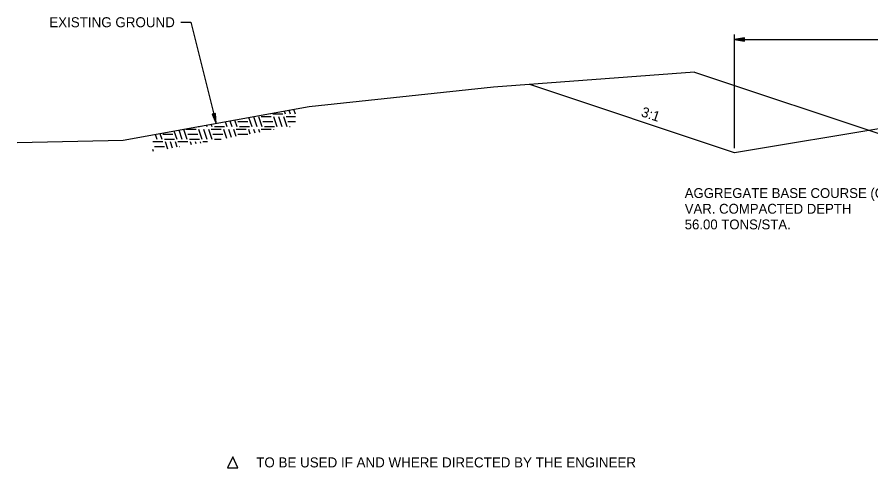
# Model space of a CAD drawing. Extents: x 1824008 to 1828864, y 689441 to 689870.
# Drawn here: x 1828711.2 to 1828762.4, y 689824.6 to 689851.6 of the extents above; entities that cross this region are included whole.
import ezdxf

# ---------------------------------------------------------------- set-up
doc = ezdxf.new("R2010")
doc.units = 0
for name, color, linetype in [('1', 7, 'Continuous'), ('19', 7, 'Continuous'), ('R_Draft', 7, 'Continuous')]:
    doc.layers.add(name, color=color, linetype=linetype)

msp = doc.modelspace()

# ---------------------------------------------------------------- linework, layer by layer
at = {"layer": '1'}
for p, q in [((1828754.22, 689843.791), (1828754.22, 689850.607)), ((1828754.82, 689850.412), (1828754.22, 689850.307)), ((1828754.22, 689850.307), (1828774.22, 689850.307)), ((1828754.22, 689850.307), (1828754.82, 689850.202)), ((1828754.82, 689850.357), (1828754.38, 689850.322)), ((1828754.38, 689850.292), (1828754.82, 689850.252)), ((1828754.82, 689850.202), (1828754.82, 689850.412)), ((1828751.824, 689848.348), (1828765.008, 689843.953)), ((1828754.22, 689843.509), (1828741.942, 689847.602)), ((1828727.883, 689845.828), (1828727.789, 689846.109)), ((1828727.883, 689845.828), (1828727.789, 689846.109)), ((1828727.883, 689845.828), (1828727.789, 689846.109)), ((1828723.09, 689845.872), (1828722.888, 689845.821)), ((1828722.888, 689845.821), (1828723.134, 689845.265)), ((1828722.933, 689845.829), (1828723.08, 689845.417)), ((1828723.105, 689845.421), (1828723.039, 689845.854)), ((1828723.134, 689845.265), (1828723.09, 689845.872)), ((1828725.286, 689845.069), (1828725.101, 689845.622)), ((1828725.286, 689845.069), (1828725.101, 689845.622)), ((1828725.286, 689845.069), (1828725.101, 689845.622)), ((1828725.586, 689845.069), (1828725.386, 689845.669)), ((1828725.586, 689845.069), (1828725.386, 689845.669)), ((1828725.586, 689845.069), (1828725.386, 689845.669)), ((1828725.886, 689845.069), (1828725.686, 689845.669)), ((1828725.886, 689845.069), (1828725.686, 689845.669)), ((1828725.886, 689845.069), (1828725.686, 689845.669)), ((1828726.436, 689845.669), (1828725.836, 689845.669)), ((1828726.436, 689845.669), (1828725.836, 689845.669)), ((1828726.436, 689845.669), (1828725.836, 689845.669)), ((1828726.386, 689845.819), (1828726.374, 689845.852)), ((1828726.386, 689845.819), (1828726.374, 689845.852)), ((1828726.386, 689845.819), (1828726.374, 689845.852)), ((1828727.136, 689845.819), (1828726.536, 689845.819)), ((1828727.136, 689845.819), (1828726.536, 689845.819)), ((1828727.136, 689845.819), (1828726.536, 689845.819)), ((1828726.786, 689845.069), (1828726.586, 689845.669)), ((1828726.786, 689845.069), (1828726.586, 689845.669)), ((1828726.786, 689845.069), (1828726.586, 689845.669)), ((1828727.086, 689845.069), (1828726.886, 689845.669)), ((1828727.086, 689845.069), (1828726.886, 689845.669)), ((1828727.086, 689845.069), (1828726.886, 689845.669)), ((1828727.386, 689845.069), (1828727.186, 689845.669)), ((1828727.386, 689845.069), (1828727.186, 689845.669)), ((1828727.386, 689845.069), (1828727.186, 689845.669)), ((1828727.286, 689845.819), (1828727.223, 689846.006)), ((1828727.286, 689845.819), (1828727.223, 689846.006)), ((1828727.286, 689845.819), (1828727.223, 689846.006)), ((1828727.386, 689845.669), (1828727.336, 689845.669)), ((1828727.386, 689845.669), (1828727.336, 689845.669)), ((1828727.386, 689845.669), (1828727.336, 689845.669)), ((1828727.883, 689845.669), (1828727.386, 689845.669)), ((1828727.883, 689845.669), (1828727.386, 689845.669)), ((1828727.883, 689845.669), (1828727.386, 689845.669)), ((1828727.586, 689845.819), (1828727.506, 689846.058)), ((1828727.586, 689845.819), (1828727.506, 689846.058)), ((1828727.586, 689845.819), (1828727.506, 689846.058)), ((1828722.286, 689845.069), (1828722.272, 689845.109)), ((1828722.286, 689845.069), (1828722.272, 689845.109)), ((1828722.286, 689845.069), (1828722.272, 689845.109)), ((1828722.586, 689845.069), (1828722.555, 689845.16)), ((1828722.586, 689845.069), (1828722.555, 689845.16)), ((1828722.586, 689845.069), (1828722.555, 689845.16)), ((1828722.886, 689845.069), (1828722.838, 689845.211)), ((1828722.886, 689845.069), (1828722.838, 689845.211)), ((1828722.886, 689845.069), (1828722.838, 689845.211)), ((1828723.786, 689845.069), (1828723.687, 689845.365)), ((1828723.786, 689845.069), (1828723.687, 689845.365)), ((1828723.786, 689845.069), (1828723.687, 689845.365)), ((1828724.086, 689845.069), (1828723.97, 689845.416)), ((1828724.086, 689845.069), (1828723.97, 689845.416)), ((1828724.086, 689845.069), (1828723.97, 689845.416)), ((1828724.386, 689845.069), (1828724.253, 689845.468)), ((1828724.386, 689845.069), (1828724.253, 689845.468)), ((1828724.386, 689845.069), (1828724.253, 689845.468)), ((1828725.036, 689845.369), (1828724.436, 689845.369)), ((1828725.036, 689845.369), (1828724.436, 689845.369)), ((1828725.036, 689845.369), (1828724.436, 689845.369)), ((1828726.536, 689845.369), (1828725.936, 689845.369)), ((1828726.536, 689845.369), (1828725.936, 689845.369)), ((1828726.536, 689845.369), (1828725.936, 689845.369)), ((1828727.883, 689845.369), (1828727.436, 689845.369)), ((1828727.883, 689845.369), (1828727.436, 689845.369)), ((1828727.883, 689845.369), (1828727.436, 689845.369)), ((1828719.586, 689844.319), (1828719.49, 689844.604)), ((1828719.586, 689844.319), (1828719.49, 689844.604)), ((1828719.586, 689844.319), (1828719.49, 689844.604)), ((1828719.886, 689844.319), (1828719.773, 689844.655)), ((1828719.886, 689844.319), (1828719.773, 689844.655)), ((1828719.886, 689844.319), (1828719.773, 689844.655)), ((1828720.536, 689844.619), (1828719.936, 689844.619)), ((1828720.536, 689844.619), (1828719.936, 689844.619)), ((1828720.536, 689844.619), (1828719.936, 689844.619)), ((1828720.786, 689844.319), (1828720.622, 689844.809)), ((1828720.786, 689844.319), (1828720.622, 689844.809)), ((1828720.786, 689844.319), (1828720.622, 689844.809)), ((1828721.086, 689844.319), (1828720.905, 689844.861)), ((1828721.086, 689844.319), (1828720.905, 689844.861)), ((1828721.086, 689844.319), (1828720.905, 689844.861)), ((1828721.386, 689844.319), (1828721.188, 689844.912)), ((1828721.386, 689844.319), (1828721.188, 689844.912)), ((1828721.386, 689844.319), (1828721.188, 689844.912)), ((1828721.386, 689844.919), (1828721.336, 689844.919)), ((1828721.386, 689844.919), (1828721.336, 689844.919)), ((1828721.386, 689844.919), (1828721.336, 689844.919)), ((1828721.936, 689844.919), (1828721.386, 689844.919)), ((1828721.936, 689844.919), (1828721.386, 689844.919)), ((1828721.936, 689844.919), (1828721.386, 689844.919)), ((1828722.036, 689844.619), (1828721.436, 689844.619)), ((1828722.036, 689844.619), (1828721.436, 689844.619)), ((1828722.036, 689844.619), (1828721.436, 689844.619)), ((1828722.136, 689845.069), (1828722.053, 689845.069)), ((1828722.136, 689845.069), (1828722.053, 689845.069)), ((1828722.136, 689845.069), (1828722.053, 689845.069)), ((1828722.286, 689844.319), (1828722.086, 689844.919)), ((1828722.286, 689844.319), (1828722.086, 689844.919)), ((1828722.286, 689844.319), (1828722.086, 689844.919)), ((1828722.586, 689844.319), (1828722.386, 689844.919)), ((1828722.586, 689844.319), (1828722.386, 689844.919)), ((1828722.586, 689844.319), (1828722.386, 689844.919)), ((1828722.886, 689844.319), (1828722.686, 689844.919)), ((1828722.886, 689844.319), (1828722.686, 689844.919)), ((1828722.886, 689844.319), (1828722.686, 689844.919)), ((1828723.436, 689844.919), (1828722.836, 689844.919)), ((1828723.436, 689844.919), (1828722.836, 689844.919)), ((1828723.436, 689844.919), (1828722.836, 689844.919)), ((1828723.536, 689844.619), (1828722.936, 689844.619)), ((1828723.536, 689844.619), (1828722.936, 689844.619)), ((1828723.536, 689844.619), (1828722.936, 689844.619)), ((1828723.636, 689845.069), (1828723.036, 689845.069)), ((1828723.636, 689845.069), (1828723.036, 689845.069)), ((1828723.636, 689845.069), (1828723.036, 689845.069)), ((1828723.765, 689844.379), (1828723.586, 689844.919)), ((1828723.765, 689844.379), (1828723.586, 689844.919)), ((1828723.765, 689844.379), (1828723.586, 689844.919)), ((1828724.048, 689844.431), (1828723.886, 689844.919)), ((1828724.048, 689844.431), (1828723.886, 689844.919)), ((1828724.048, 689844.431), (1828723.886, 689844.919)), ((1828724.331, 689844.482), (1828724.186, 689844.919)), ((1828724.331, 689844.482), (1828724.186, 689844.919)), ((1828724.331, 689844.482), (1828724.186, 689844.919)), ((1828724.386, 689844.919), (1828724.336, 689844.919)), ((1828724.386, 689844.919), (1828724.336, 689844.919)), ((1828724.386, 689844.919), (1828724.336, 689844.919)), ((1828724.936, 689844.919), (1828724.386, 689844.919)), ((1828724.936, 689844.919), (1828724.386, 689844.919)), ((1828724.936, 689844.919), (1828724.386, 689844.919)), ((1828725.036, 689844.619), (1828724.436, 689844.619)), ((1828725.036, 689844.619), (1828724.436, 689844.619)), ((1828725.036, 689844.619), (1828724.436, 689844.619)), ((1828725.136, 689845.069), (1828724.536, 689845.069)), ((1828725.136, 689845.069), (1828724.536, 689845.069)), ((1828725.136, 689845.069), (1828724.536, 689845.069)), ((1828725.18, 689844.636), (1828725.086, 689844.919)), ((1828725.18, 689844.636), (1828725.086, 689844.919)), ((1828725.18, 689844.636), (1828725.086, 689844.919)), ((1828725.463, 689844.687), (1828725.386, 689844.919)), ((1828725.463, 689844.687), (1828725.386, 689844.919)), ((1828725.463, 689844.687), (1828725.386, 689844.919)), ((1828725.746, 689844.738), (1828725.686, 689844.919)), ((1828725.746, 689844.738), (1828725.686, 689844.919)), ((1828725.746, 689844.738), (1828725.686, 689844.919)), ((1828726.436, 689844.919), (1828725.836, 689844.919)), ((1828726.436, 689844.919), (1828725.836, 689844.919)), ((1828726.436, 689844.919), (1828725.836, 689844.919)), ((1828726.636, 689845.069), (1828726.036, 689845.069)), ((1828726.636, 689845.069), (1828726.036, 689845.069)), ((1828726.636, 689845.069), (1828726.036, 689845.069)), ((1828726.594, 689844.892), (1828726.586, 689844.919)), ((1828726.594, 689844.892), (1828726.586, 689844.919)), ((1828726.594, 689844.892), (1828726.586, 689844.919)), ((1828727.568, 689845.069), (1828727.536, 689845.069)), ((1828727.568, 689845.069), (1828727.536, 689845.069)), ((1828727.568, 689845.069), (1828727.536, 689845.069)), ((1828719.936, 689844.169), (1828719.336, 689844.169)), ((1828719.936, 689844.169), (1828719.336, 689844.169)), ((1828719.936, 689844.169), (1828719.336, 689844.169)), ((1828720.636, 689844.319), (1828720.036, 689844.319)), ((1828720.636, 689844.319), (1828720.036, 689844.319)), ((1828720.636, 689844.319), (1828720.036, 689844.319)), ((1828720.229, 689843.738), (1828720.086, 689844.169)), ((1828720.229, 689843.738), (1828720.086, 689844.169)), ((1828720.229, 689843.738), (1828720.086, 689844.169)), ((1828720.512, 689843.789), (1828720.386, 689844.169)), ((1828720.512, 689843.789), (1828720.386, 689844.169)), ((1828720.512, 689843.789), (1828720.386, 689844.169)), ((1828720.795, 689843.841), (1828720.686, 689844.169)), ((1828720.795, 689843.841), (1828720.686, 689844.169)), ((1828720.795, 689843.841), (1828720.686, 689844.169)), ((1828721.386, 689844.169), (1828720.836, 689844.169)), ((1828721.386, 689844.169), (1828720.836, 689844.169)), ((1828721.386, 689844.169), (1828720.836, 689844.169)), ((1828721.436, 689844.169), (1828721.386, 689844.169)), ((1828721.436, 689844.169), (1828721.386, 689844.169)), ((1828721.436, 689844.169), (1828721.386, 689844.169)), ((1828722.136, 689844.319), (1828721.536, 689844.319)), ((1828722.136, 689844.319), (1828721.536, 689844.319)), ((1828722.136, 689844.319), (1828721.536, 689844.319)), ((1828721.644, 689843.995), (1828721.586, 689844.169)), ((1828721.644, 689843.995), (1828721.586, 689844.169)), ((1828721.644, 689843.995), (1828721.586, 689844.169)), ((1828721.927, 689844.046), (1828721.886, 689844.169)), ((1828721.927, 689844.046), (1828721.886, 689844.169)), ((1828721.927, 689844.046), (1828721.886, 689844.169)), ((1828722.209, 689844.097), (1828722.186, 689844.169)), ((1828722.209, 689844.097), (1828722.186, 689844.169)), ((1828722.209, 689844.097), (1828722.186, 689844.169)), ((1828722.604, 689844.169), (1828722.336, 689844.169)), ((1828722.604, 689844.169), (1828722.336, 689844.169)), ((1828722.604, 689844.169), (1828722.336, 689844.169)), ((1828723.431, 689844.319), (1828723.036, 689844.319)), ((1828723.431, 689844.319), (1828723.036, 689844.319)), ((1828723.431, 689844.319), (1828723.036, 689844.319)), ((1828719.38, 689843.584), (1828719.336, 689843.717)), ((1828719.38, 689843.584), (1828719.336, 689843.717)), ((1828719.38, 689843.584), (1828719.336, 689843.717)), ((1828720.036, 689843.869), (1828719.436, 689843.869)), ((1828720.036, 689843.869), (1828719.436, 689843.869)), ((1828720.036, 689843.869), (1828719.436, 689843.869)), ((1828720.95, 689843.869), (1828720.936, 689843.869)), ((1828720.95, 689843.869), (1828720.936, 689843.869)), ((1828720.95, 689843.869), (1828720.936, 689843.869))]:
    msp.add_line(p, q, dxfattribs=at)
for points in [[(1828721.022, 689851.338), (1828721.622, 689851.338), (1828723.134, 689845.265)], [(1828751.824, 689848.348), (1828739.772, 689847.438), (1828728.716, 689846.277), (1828717.551, 689844.253), (1828711.19, 689844.117)]]:
    msp.add_lwpolyline(points, dxfattribs=at)
at = {"layer": '19'}
for p, q in [((1828770.22, 689846.176), (1828754.22, 689843.509)), ((1828724.134, 689825.297), (1828723.816, 689824.626)), ((1828724.427, 689824.626), (1828724.134, 689825.297)), ((1828723.816, 689824.626), (1828724.427, 689824.626))]:
    msp.add_line(p, q, dxfattribs=at)
at = {"layer": 'R_Draft'}
for p, q in [((1828727.883, 689845.828), (1828727.789, 689846.109)), ((1828725.286, 689845.069), (1828725.101, 689845.622)), ((1828725.586, 689845.069), (1828725.386, 689845.669)), ((1828725.886, 689845.069), (1828725.686, 689845.669)), ((1828726.436, 689845.669), (1828725.836, 689845.669)), ((1828726.386, 689845.819), (1828726.374, 689845.852)), ((1828727.136, 689845.819), (1828726.536, 689845.819)), ((1828726.786, 689845.069), (1828726.586, 689845.669)), ((1828727.086, 689845.069), (1828726.886, 689845.669)), ((1828727.386, 689845.069), (1828727.186, 689845.669)), ((1828727.286, 689845.819), (1828727.223, 689846.006)), ((1828727.386, 689845.669), (1828727.336, 689845.669)), ((1828727.883, 689845.669), (1828727.386, 689845.669)), ((1828727.586, 689845.819), (1828727.506, 689846.058)), ((1828722.286, 689845.069), (1828722.272, 689845.109)), ((1828722.586, 689845.069), (1828722.555, 689845.16)), ((1828722.886, 689845.069), (1828722.838, 689845.211)), ((1828723.786, 689845.069), (1828723.687, 689845.365)), ((1828724.086, 689845.069), (1828723.97, 689845.416)), ((1828724.386, 689845.069), (1828724.253, 689845.468)), ((1828725.036, 689845.369), (1828724.436, 689845.369)), ((1828726.536, 689845.369), (1828725.936, 689845.369)), ((1828727.883, 689845.369), (1828727.436, 689845.369)), ((1828719.586, 689844.319), (1828719.49, 689844.604)), ((1828719.886, 689844.319), (1828719.773, 689844.655)), ((1828720.536, 689844.619), (1828719.936, 689844.619)), ((1828720.786, 689844.319), (1828720.622, 689844.809)), ((1828721.086, 689844.319), (1828720.905, 689844.861)), ((1828721.386, 689844.319), (1828721.188, 689844.912)), ((1828721.386, 689844.919), (1828721.336, 689844.919)), ((1828721.936, 689844.919), (1828721.386, 689844.919)), ((1828722.036, 689844.619), (1828721.436, 689844.619)), ((1828722.136, 689845.069), (1828722.053, 689845.069)), ((1828722.286, 689844.319), (1828722.086, 689844.919)), ((1828722.586, 689844.319), (1828722.386, 689844.919)), ((1828722.886, 689844.319), (1828722.686, 689844.919)), ((1828723.436, 689844.919), (1828722.836, 689844.919)), ((1828723.536, 689844.619), (1828722.936, 689844.619)), ((1828723.636, 689845.069), (1828723.036, 689845.069)), ((1828723.765, 689844.379), (1828723.586, 689844.919)), ((1828724.048, 689844.431), (1828723.886, 689844.919)), ((1828724.331, 689844.482), (1828724.186, 689844.919)), ((1828724.386, 689844.919), (1828724.336, 689844.919)), ((1828724.936, 689844.919), (1828724.386, 689844.919)), ((1828725.036, 689844.619), (1828724.436, 689844.619)), ((1828725.136, 689845.069), (1828724.536, 689845.069)), ((1828725.18, 689844.636), (1828725.086, 689844.919)), ((1828725.463, 689844.687), (1828725.386, 689844.919)), ((1828725.746, 689844.738), (1828725.686, 689844.919)), ((1828726.436, 689844.919), (1828725.836, 689844.919)), ((1828726.636, 689845.069), (1828726.036, 689845.069)), ((1828726.594, 689844.892), (1828726.586, 689844.919)), ((1828727.568, 689845.069), (1828727.536, 689845.069)), ((1828719.936, 689844.169), (1828719.336, 689844.169)), ((1828720.636, 689844.319), (1828720.036, 689844.319)), ((1828720.229, 689843.738), (1828720.086, 689844.169)), ((1828720.512, 689843.789), (1828720.386, 689844.169)), ((1828720.795, 689843.841), (1828720.686, 689844.169)), ((1828721.386, 689844.169), (1828720.836, 689844.169)), ((1828721.436, 689844.169), (1828721.386, 689844.169)), ((1828722.136, 689844.319), (1828721.536, 689844.319)), ((1828721.644, 689843.995), (1828721.586, 689844.169)), ((1828721.927, 689844.046), (1828721.886, 689844.169)), ((1828722.209, 689844.097), (1828722.186, 689844.169)), ((1828722.604, 689844.169), (1828722.336, 689844.169)), ((1828723.431, 689844.319), (1828723.036, 689844.319)), ((1828719.38, 689843.584), (1828719.336, 689843.717)), ((1828720.036, 689843.869), (1828719.436, 689843.869)), ((1828720.95, 689843.869), (1828720.936, 689843.869))]:
    msp.add_line(p, q, dxfattribs=at)

# ---------------------------------------------------------------- texts
at = {"layer": '1'}
msp.add_text('3:1', height=0.6, rotation=341.5651, dxfattribs=at).set_placement((1828748.575, 689845.716))
at = {"layer": '19'}
for s, p in [('AGGREGATE BASE COURSE (CLASS 7)', (1828751.238, 689840.804)), ('VAR. COMPACTED DEPTH', (1828751.238, 689839.864)), ('56.00 TONS/STA.', (1828751.238, 689838.924))]:
    msp.add_text(s, height=0.59001, rotation=360, dxfattribs=at).set_placement(p)
msp.add_text('TO BE USED IF AND WHERE DIRECTED BY THE ENGINEER', height=0.6, dxfattribs=at).set_placement((1828725.536, 689824.656))
at = {"layer": 'R_Draft'}
msp.add_text('EXISTING GROUND', height=0.6, dxfattribs=at).set_placement((1828713.12, 689851.038))

doc.saveas('drawing.dxf')
